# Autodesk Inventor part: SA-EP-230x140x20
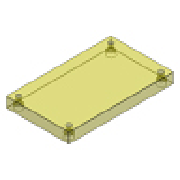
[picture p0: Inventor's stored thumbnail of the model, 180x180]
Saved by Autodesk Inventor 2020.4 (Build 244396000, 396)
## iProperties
Created: 2019-01
Part Number: SA-EP-230x140x20
Material: S 55 C
Description: Ejector Plate
Document SubType Name: Modeling
Designer: mel
Standard Revision: 1
Manufacturer: FUTABA
Language: fr-FR
Size Designation: 230x140x20
Categories: <MemberInstance><Categories><Category DisplayName="Moule" InternalName="349578f2-f4d4-4954-8c09-8e99297a61c0" Mnemonic="MOLD"><Category DisplayName="Plaque de m
Density: 7.85 g/cm^3
Appearance: Clear - Yellow
IsCustomPart: 1
Author: mel
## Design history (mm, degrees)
sketch "Sketch1"
  geometry: L1 (-70, 115)-(70, 115); L2 (70, 115)-(70, -115); L3 (70, -115)-(-70, -115); L4 (-70, -115)-(-70, 115); 4 further points
  constraints: 8 end point, 2 midpoint, 2 parallel, 1 horizontal, 1 horizontal alignment, 1 perpendicular, 1 vertical alignment
  dimensions: "d74" = 60 horizontal distance of point (0, 0) point (-60, 105) (= 0.5 x S2_W); "d75" = 105 vertical distance of point (0, 0) point (-60, 105) (= 0.5 x S2_L); "d92" = 140 distance between parallel lines of L2 L4 (= W_); "d93" = 230 distance between parallel lines of L3 L1 (= L)
extrude "Extrusion1" new body sketch "Sketch1" distance "d20" = 20 (= H_); taper "d30" = 0 deg
hole "Hole1" sketch "Sketch1" diameter "d76" = 9 (= S2_d1); stored, may be unused: countersink angle "d80" = 90 deg, drill point angle "d82" = 0 deg; dims "d77" = 6, "d78" = 15 (= S2_d2), "d79" = 9 (= S2_k), "d81" = 20 (= H_)
pattern_linear "Rectangular Pattern1" dims "d85" = 210 (computed from S2_L, Nl), "d88" = 120 (computed from S2_W, Nw)
chamfer "Chamfer1" distance "d89" = 0.5; stored, may be unused: second distance "d90" = 2, angle "d91" = 45 deg
body "Solid1"
other parameters: "L" = 230 [user parameter; used in 1 equation term], "W_" = 140 [user parameter; used in 1 equation term], "H_" = 20 [user parameter; used in 2 equation terms], "S2_d1" = 9 [user parameter; used in 1 equation term], "S2_d2" = 15 [user parameter; used in 1 equation term], "S2_k" = 9 [user parameter; used in 1 equation term]
